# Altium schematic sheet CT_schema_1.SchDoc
size 577 x 532 mm
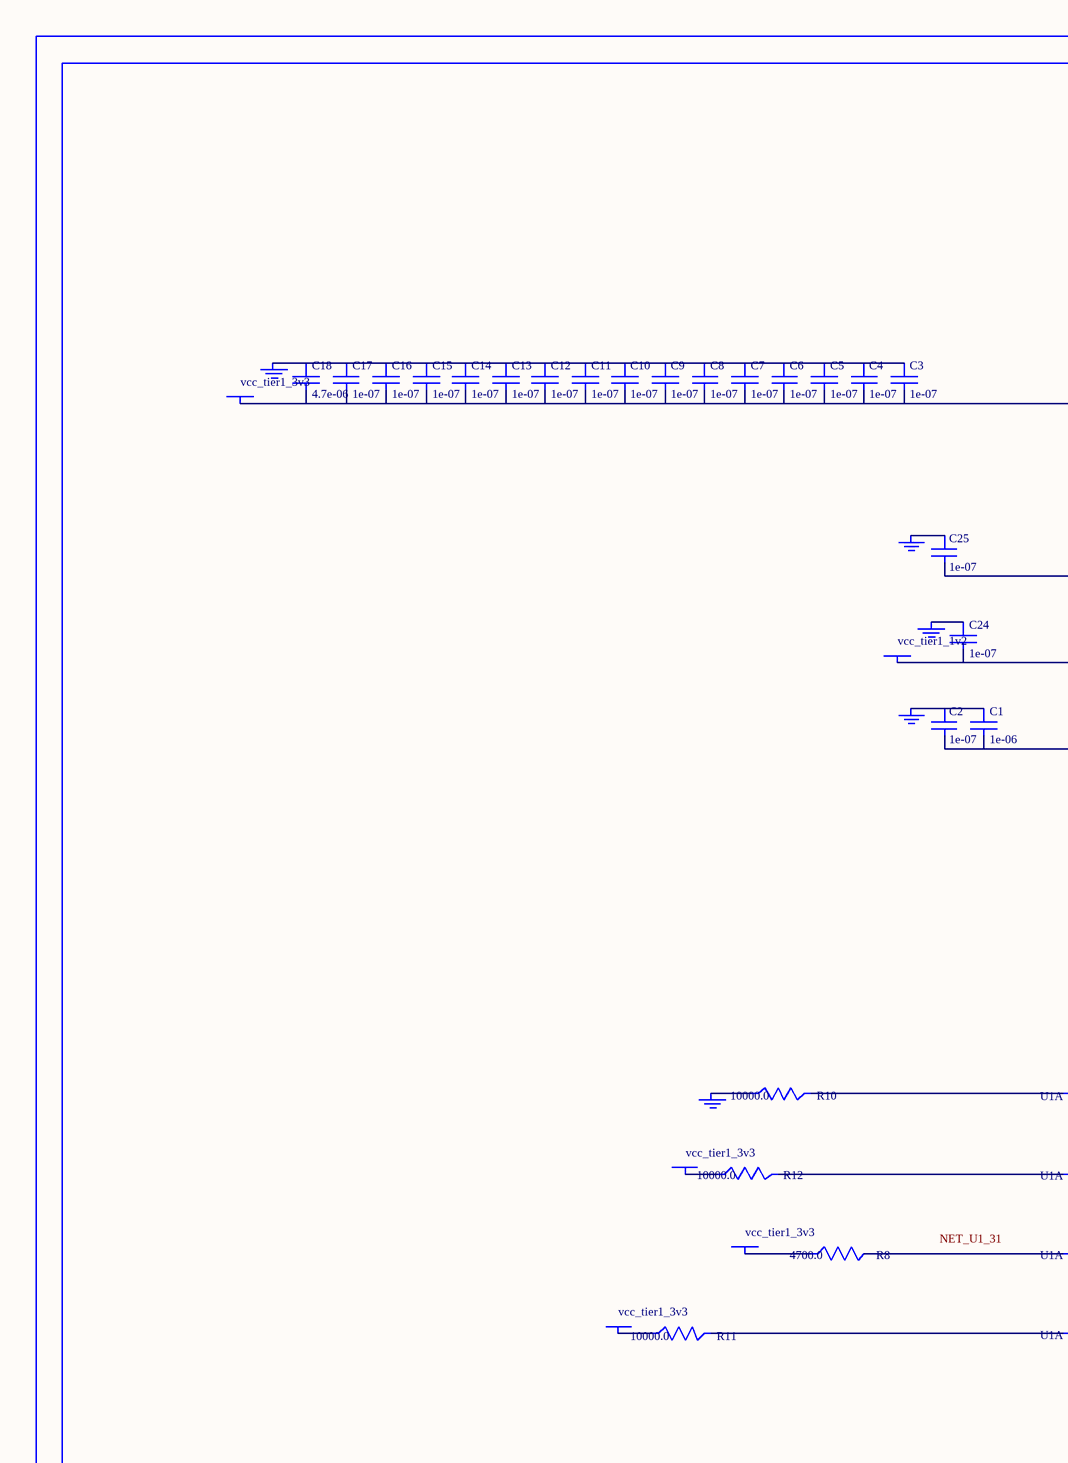
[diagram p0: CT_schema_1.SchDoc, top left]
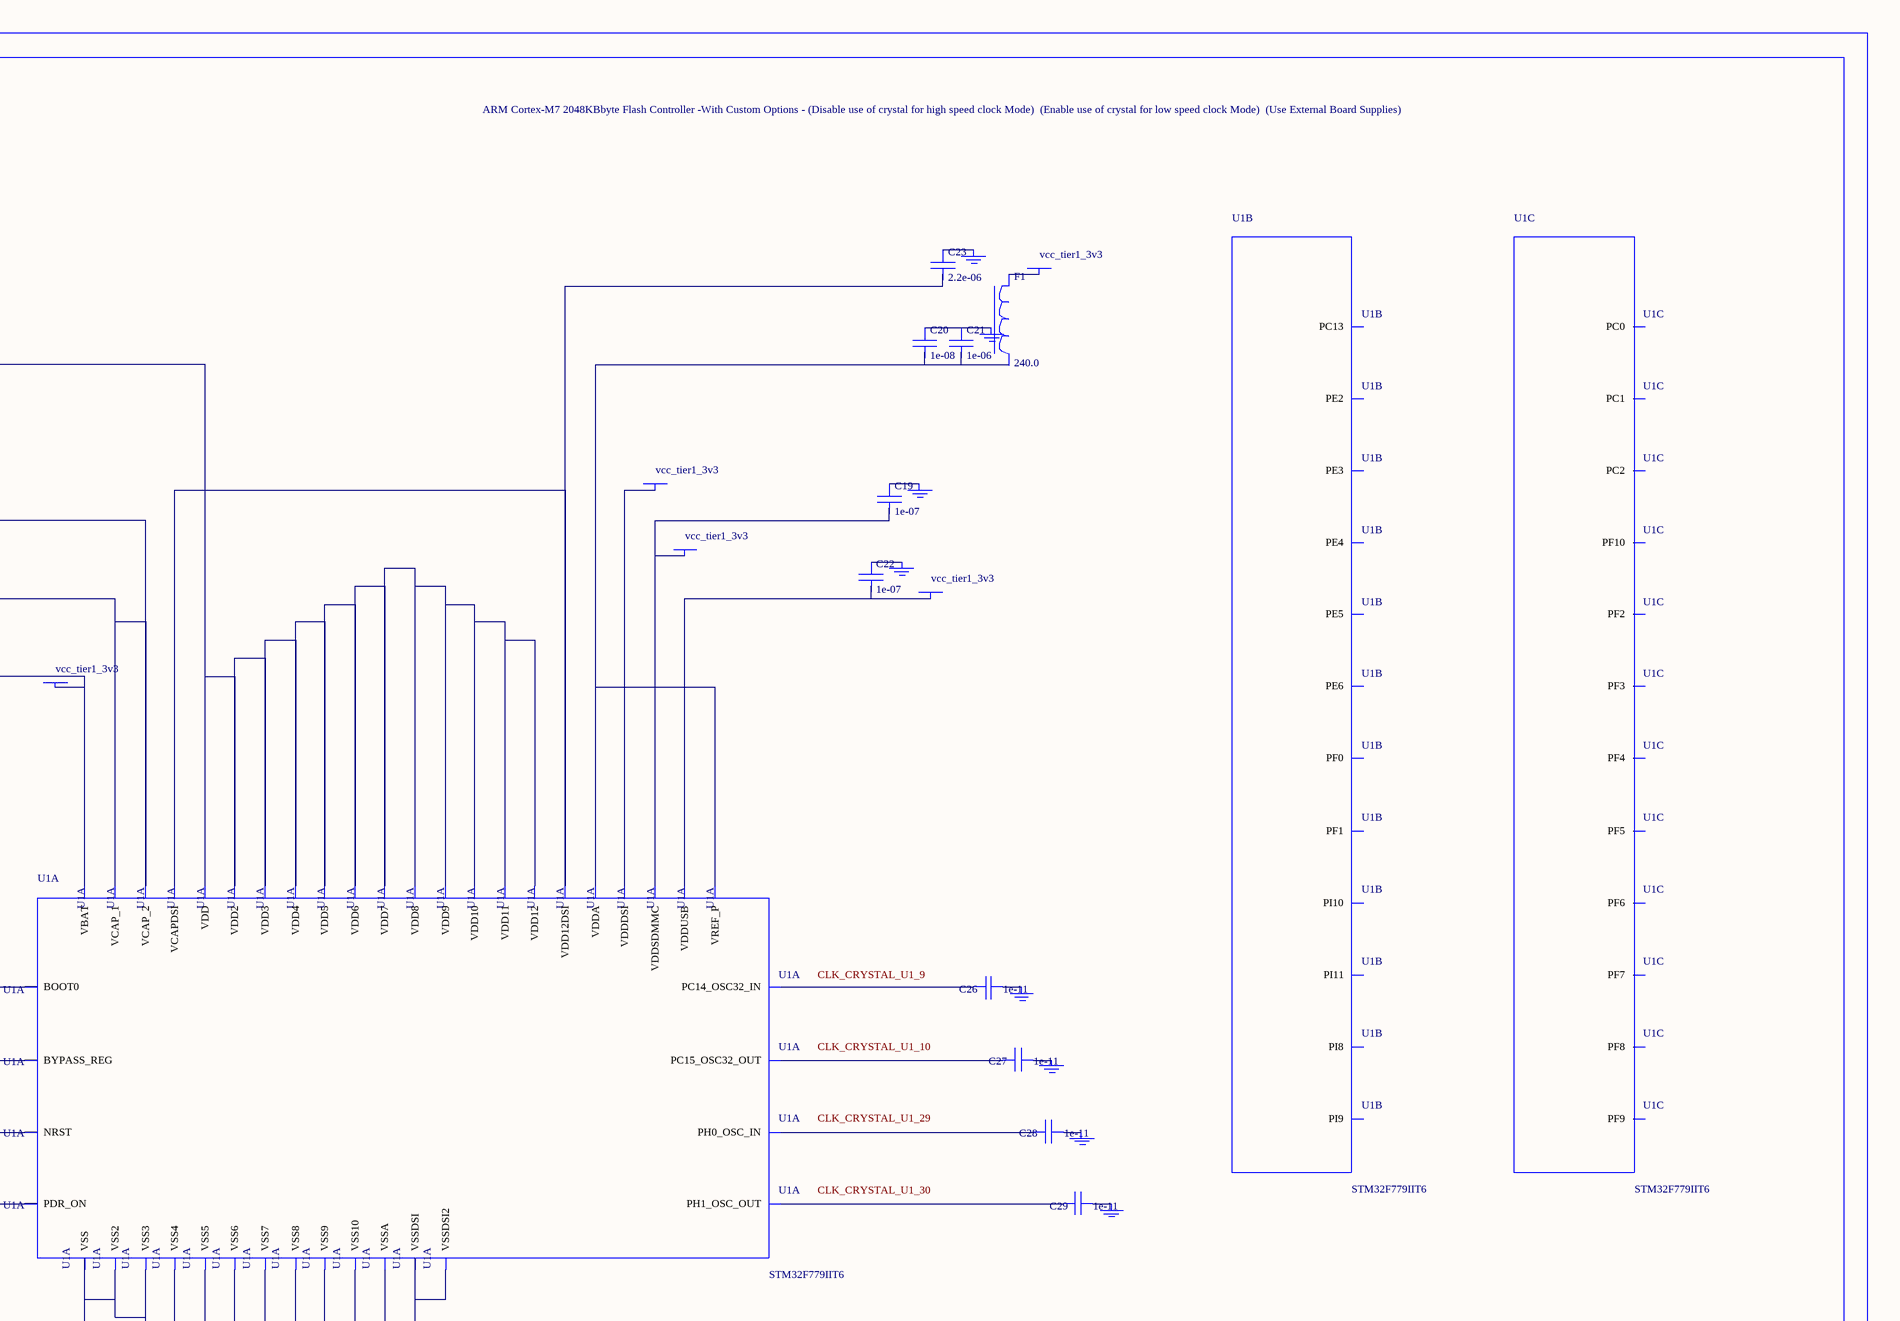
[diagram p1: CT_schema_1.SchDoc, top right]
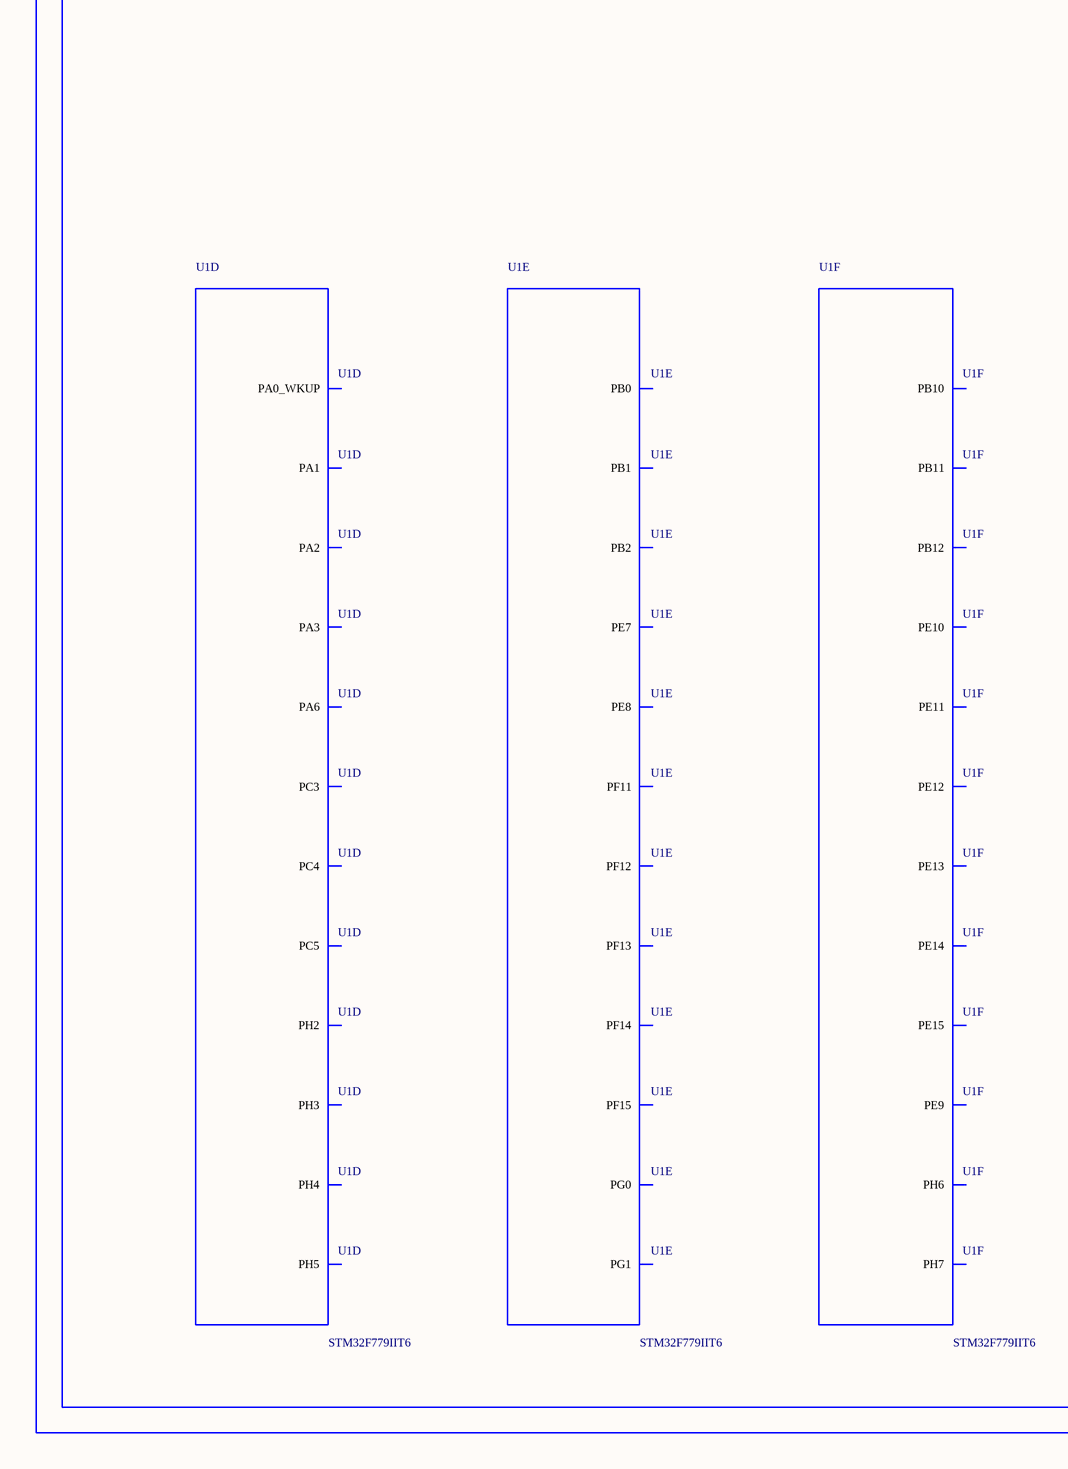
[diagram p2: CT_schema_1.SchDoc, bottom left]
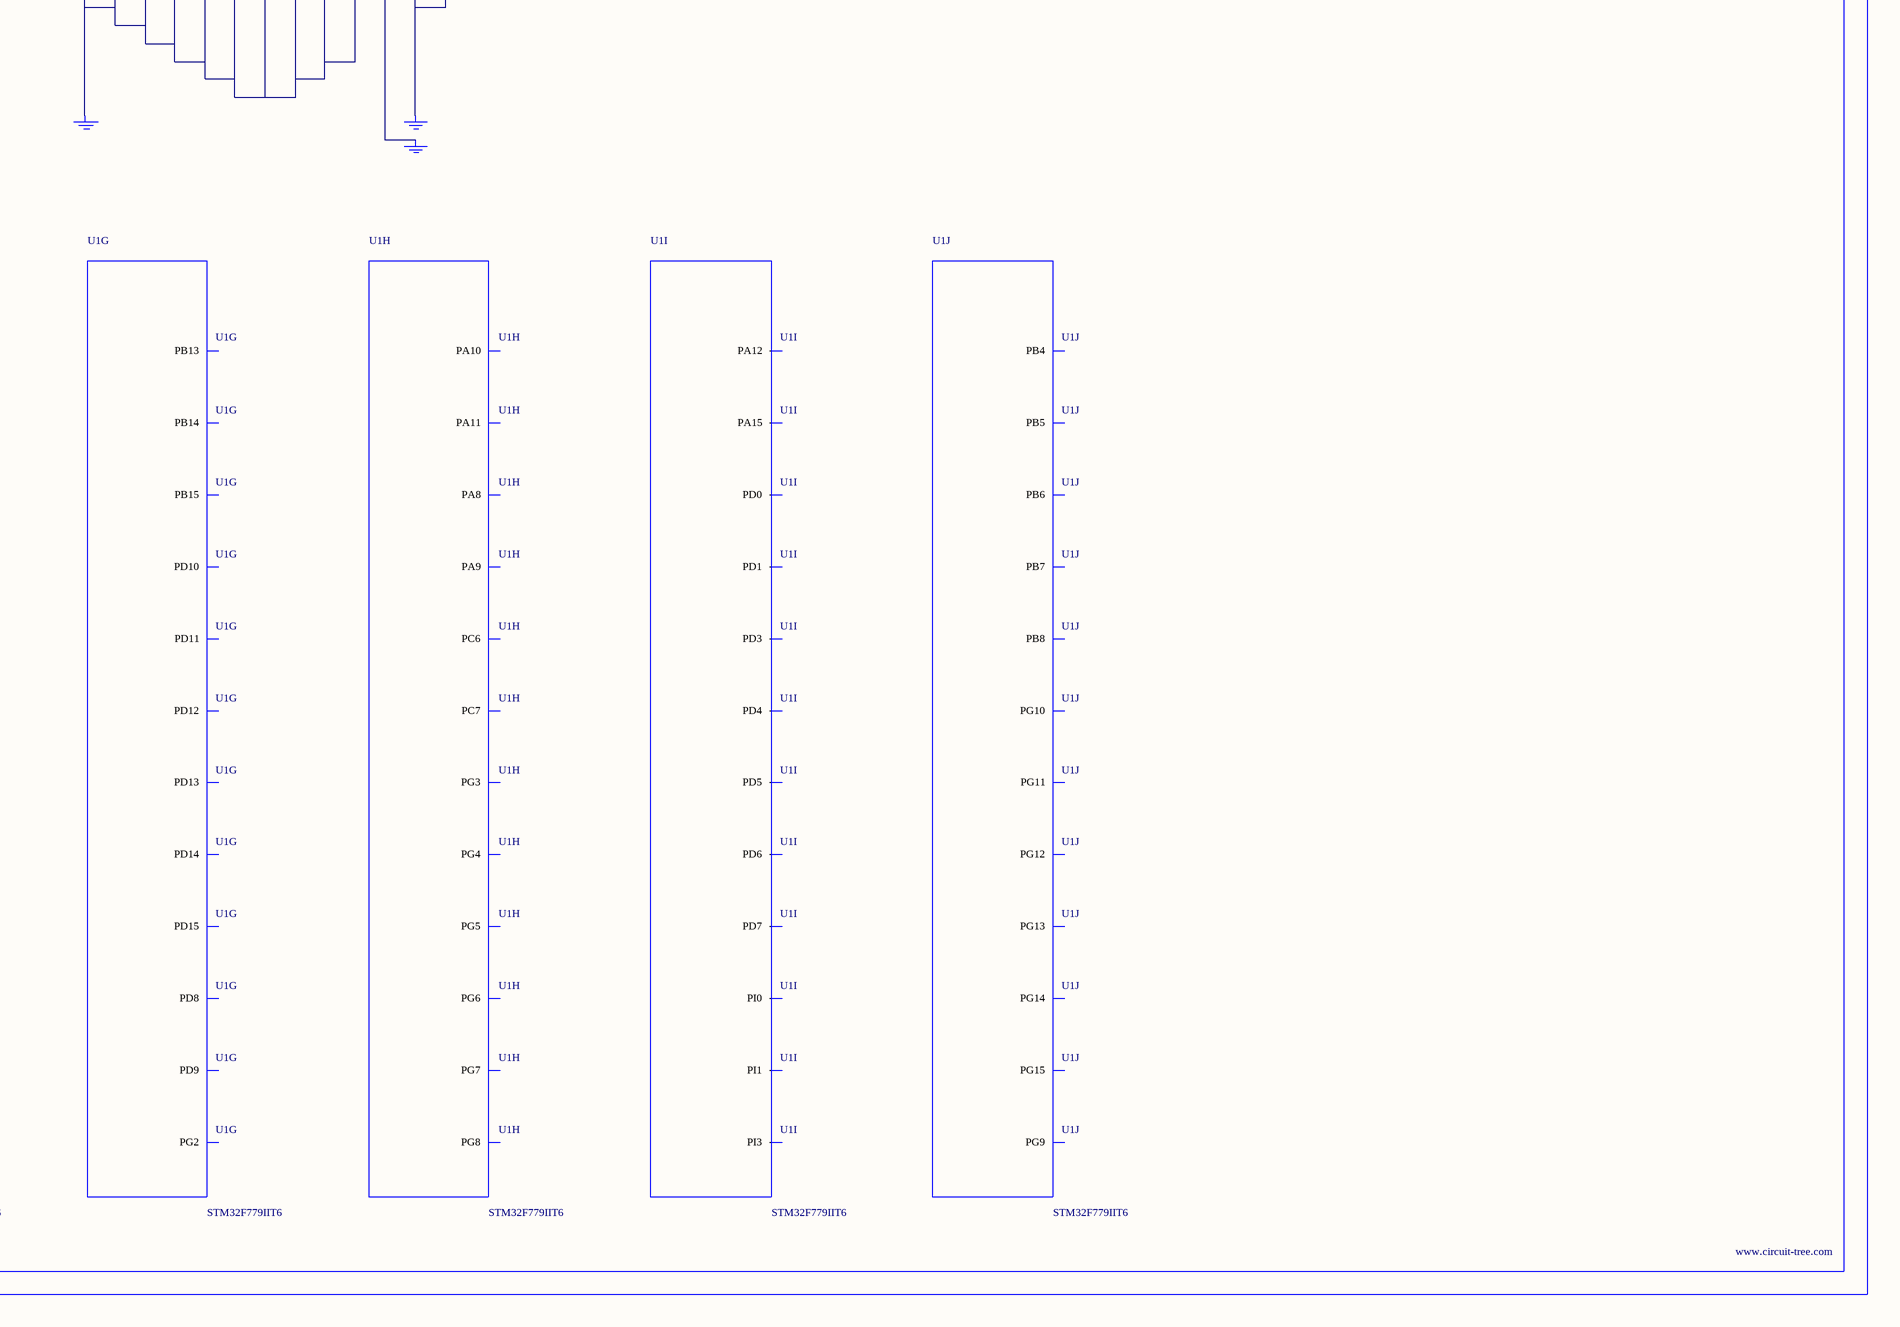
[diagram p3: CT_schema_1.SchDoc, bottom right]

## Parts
BORDER0  (no value)
C1  1e-06  [C0603]
C2  1e-07  [C0603]
C3  1e-07  [C0603]
C4  1e-07  [C0603]
C5  1e-07  [C0603]
C6  1e-07  [C0603]
C7  1e-07  [C0603]
C8  1e-07  [C0603]
C9  1e-07  [C0603]
C10  1e-07  [C0603]
C11  1e-07  [C0603]
C12  1e-07  [C0603]
C13  1e-07  [C0603]
C14  1e-07  [C0603]
C15  1e-07  [C0603]
C16  1e-07  [C0603]
C17  1e-07  [C0603]
C18  4.7e-06  [C0603]
C19  1e-07  [C0603]
C20  1e-08  [C0603]
C21  1e-06  [C0603]
C22  1e-07  [C0603]
C23  2.2e-06  [C0603]
C24  1e-07  [C0603]
C25  1e-07  [C0603]
C26  1e-11  [C0402]
C27  1e-11  [C0402]
C28  1e-11  [C0402]
C29  1e-11  [C0402]
F1  240.0  [L0603]
GND_INSTANCE_0_0  (no value)
GND_INSTANCE_0_1  (no value)
GND_INSTANCE_0_2  (no value)
GND_INSTANCE_0_3  (no value)
GND_INSTANCE_0_4  (no value)
GND_INSTANCE_0_5  (no value)
GND_INSTANCE_0_6  (no value)
GND_INSTANCE_0_7  (no value)
GND_INSTANCE_0_8  (no value)
GND_INSTANCE_0_9  (no value)
GND_INSTANCE_0_10  (no value)
GND_INSTANCE_0_11  (no value)
GND_INSTANCE_0_12  (no value)
GND_INSTANCE_0_13  (no value)
GND_INSTANCE_0_14  (no value)
GND_INSTANCE_0_15  (no value)
POWER_INSTANCE_0_0  vcc_tier1_3v3
POWER_INSTANCE_0_1  vcc_tier1_3v3
POWER_INSTANCE_0_2  vcc_tier1_3v3
POWER_INSTANCE_0_3  vcc_tier1_3v3
POWER_INSTANCE_0_4  vcc_tier1_1v2
POWER_INSTANCE_0_5  vcc_tier1_3v3
POWER_INSTANCE_0_6  vcc_tier1_3v3
POWER_INSTANCE_0_7  vcc_tier1_3v3
POWER_INSTANCE_0_8  vcc_tier1_3v3
POWER_INSTANCE_0_9  vcc_tier1_3v3
R8  4700.0  [R0603]
R10  10000.0  [R0603]
R11  10000.0  [R0603]
R12  10000.0  [R0603]
U1  STM32F779IIT6  [LQFP176]  (parts A,B,C,D,E,F,G,H,I,J of 14)

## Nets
NetC1_1: C1.1 C2.1 GND_INSTANCE_0_0.0(GND)
NetC1_2: C1.2 C2.2 POWER_INSTANCE_0_0.0(PWR) U1.6(VBAT)
NetC3_1: C3.1 C4.1 C5.1 C6.1 C7.1 C8.1 C9.1 C10.1 C11.1 C12.1 C13.1 C14.1 C15.1 C16.1 C17.1 C18.1 GND_INSTANCE_0_3.0(GND)
NetC3_2: C3.2 C4.2 C5.2 C6.2 C7.2 C8.2 C9.2 C10.2 C11.2 C12.2 C13.2 C14.2 C15.2 C16.2 C17.2 C18.2 POWER_INSTANCE_0_1.0(PWR) U1.15(VDD) U1.23(VDD2) U1.36(VDD3) U1.49(VDD4) U1.62(VDD5) U1.72(VDD6) U1.82(VDD7) U1.96(VDD8) U1.131(VDD9) U1.136(VDD10) U1.159(VDD11) U1.172(VDD12)
NetC19_1: C19.1 GND_INSTANCE_0_12.0(GND)
NetC19_2: C19.2 POWER_INSTANCE_0_7.0(PWR) U1.149(VDDSDMMC)
NetC20_1: C20.1 C21.1 GND_INSTANCE_0_7.0(GND)
NetC20_2: C20.2 C21.2 U1.38(VREF_P) U1.39(VDDA)
NetC22_1: C22.1 GND_INSTANCE_0_10.0(GND)
NetC22_2: C22.2 POWER_INSTANCE_0_6.0(PWR) U1.118(VDDUSB)
NetC23_1: C23.1 GND_INSTANCE_0_9.0(GND)
NetC23_2: C23.2 U1.100(VCAPDSI) U1.106(VDD12DSI)
NetC24_1: C24.1 GND_INSTANCE_0_8.0(GND)
NetC24_2: C24.2 C25.2 POWER_INSTANCE_0_4.0(PWR) U1.81(VCAP_1) U1.129(VCAP_2)
NetC25_1: C25.1 GND_INSTANCE_0_11.0(GND)
NetC26_1: C26.1 GND_INSTANCE_0_1.0(GND)
NetC26_2: C26.2 U1.9(PC14_OSC32_IN)
NetC27_1: C27.1 GND_INSTANCE_0_2.0(GND)
NetC27_2: C27.2 U1.10(PC15_OSC32_OUT)
NetC28_1: C28.1 GND_INSTANCE_0_4.0(GND)
NetC28_2: C28.2 U1.29(PH0_OSC_IN)
NetC29_1: C29.1 GND_INSTANCE_0_5.0(GND)
NetC29_2: C29.2 U1.30(PH1_OSC_OUT)
NetF1_1: F1.1 POWER_INSTANCE_0_2.0(PWR)
NetGND_INSTANCE_0_6_0: GND_INSTANCE_0_6.0(GND) U1.37(VSSA)
NetGND_INSTANCE_0_13_0: GND_INSTANCE_0_13.0(GND) R10.1
NetGND_INSTANCE_0_14_0: GND_INSTANCE_0_14.0(GND) U1.14(VSS) U1.22(VSS2) U1.61(VSS3) U1.71(VSS4) U1.95(VSS5) U1.117(VSS6) U1.130(VSS7) U1.135(VSS8) U1.148(VSS9) U1.158(VSS10)
NetGND_INSTANCE_0_15_0: GND_INSTANCE_0_15.0(GND) U1.103(VSSDSI) U1.109(VSSDSI2)
NetPOWER_INSTANCE_0_3_0: POWER_INSTANCE_0_3.0(PWR) R12.1
NetPOWER_INSTANCE_0_5_0: POWER_INSTANCE_0_5.0(PWR) U1.99(VDDDSI)
NetPOWER_INSTANCE_0_8_0: POWER_INSTANCE_0_8.0(PWR) R11.1
NetPOWER_INSTANCE_0_9_0: POWER_INSTANCE_0_9.0(PWR) R8.1
NetR8_2: R8.2 U1.31(NRST)
NetR10_2: R10.2 U1.166(BOOT0)
NetR11_2: R11.2 U1.171(PDR_ON)
NetR12_2: R12.2 U1.48(BYPASS_REG)

Not connected (* = marked no-connect by the designer): F1 2; U1 1(PE2) 2(PE3) 3(PE4) 4(PE5) 5(PE6) 7(PI8) 8(PC13) 11(PI9) 12(PI10) 13(PI11) 16(PF0) 17(PF1) 18(PF2) 19(PF3) 20(PF4) 21(PF5) 24(PF6) 25(PF7) 26(PF8) 27(PF9) 28(PF10) 32(PC0) 33(PC1) 34(PC2) 35(PC3) 40(PA0_WKUP) 41(PA1) 42(PA2) 43(PH2) 44(PH3) 45(PH4) 46(PH5) 47(PA3) 52(PA6) 54(PC4) 55(PC5) 56(PB0) 57(PB1) 58(PB2) 59(PF11) 60(PF12) 63(PF13) 64(PF14) 65(PF15) 66(PG0) 67(PG1) 68(PE7) 69(PE8) 70(PE9) 73(PE10) 74(PE11) 75(PE12) 76(PE13) 77(PE14) 78(PE15) 79(PB10) 80(PB11) 83(PH6) 84(PH7) 85(PB12) 86(PB13) 87(PB14) 88(PB15) 89(PD8) 90(PD9) 91(PD10) 92(PD11) 93(PD12) 94(PD13) 97(PD14) 98(PD15) 110(PG2) 111(PG3) 112(PG4) 113(PG5) 114(PG6) 115(PG7) 116(PG8) 119(PC6) 120(PC7) 123(PA8) 124(PA9) 125(PA10) 126(PA11) 127(PA12) 132(PI0) 133(PI1) 134(PI3) 138(PA15) 142(PD0) 143(PD1) 145(PD3) 146(PD4) 147(PD5) 150(PD6) 151(PD7) 152(PG9) 153(PG10) 154(PG11) 155(PG12) 156(PG13) 157(PG14) 160(PG15) 162(PB4) 163(PB5) 164(PB6) 165(PB7) 167(PB8)

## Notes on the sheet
- Labels drawn without touching a wire or pin: CLK_CRYSTAL_U1_9, CLK_CRYSTAL_U1_10, CLK_CRYSTAL_U1_29, CLK_CRYSTAL_U1_30, NET_U1_31

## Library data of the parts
BORDER0 = BORDER_PAGE0
C1 C21 = C0603C105K3RACTU
C2-C17 C19 C22 C24 C25 = 06035C104K4Z2A
C18 = GRM188R6YA475KE15D
C20 = 06035C103K4Z2A
C23 = C0603C225K8RACTU
C26-C29 = C0402C100K3GACTU
F1 = Z0603C241ASMST
GND_INSTANCE_0_0-GND_INSTANCE_0_15 = GND
POWER_INSTANCE_0_0-POWER_INSTANCE_0_9 = PWR
R8 = RC0603JR-074K7L
R10-R12 = RC0603JR-0710KL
